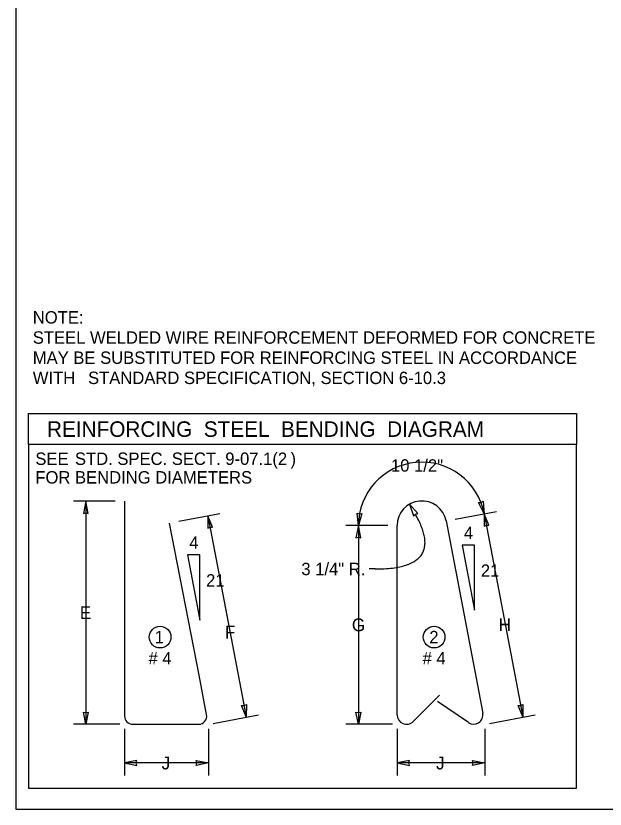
# Model space of a CAD drawing. Extents: x 99862 to 103680, y 99470 to 102076.
# Drawn here: x 99862 to 100621, y 100000 to 101023 of the extents above; entities that cross this region are included whole.
import ezdxf

# ---------------------------------------------------------------- set-up
doc = ezdxf.new("R2010")
doc.units = 0
for name, color, linetype in [('Level 1', 7, 'Continuous'), ('Level 10', 7, 'Continuous'), ('Level 15', 7, 'Continuous'), ('Level 16', 7, 'Continuous'), ('Level 20', 7, 'Continuous'), ('Level 40', 7, 'Continuous'), ('Level 60', 7, 'Continuous')]:
    doc.layers.add(name, color=color, linetype=linetype)

msp = doc.modelspace()

# ---------------------------------------------------------------- linework, layer by layer
at = {"layer": 'Level 1'}
msp.add_lwpolyline([(99862, 99999.5), (103151, 99999.5), (103151, 102075.5), (99862, 102075.5)], close=True, dxfattribs=at)
at = {"layer": 'Level 10'}
for p, q in [((100002.1, 100396.5), (100002.1, 100119.5)), ((100416.4, 100371.2), (100463.6, 100123.2)), ((100353.4, 100121), (100353.4, 100365.2)), ((100407.8, 100146.5), (100373.9, 100112.5)), ((100445.1, 100111.1), (100405.4, 100138.1)), ((100012.6, 100109), (100097.5, 100109))]:
    msp.add_line(p, q, dxfattribs=at)
msp.add_lwpolyline([(100107.8, 100121.5), (100098.1, 100172.2), (100060, 100368.5)], dxfattribs=at)
for centre, radius, start, end in [((100385.2, 100365.2), 31.8, 10.7843, 180), ((100012.6, 100119.5), 10.5, 180, 270), ((100097.5, 100119.5), 10.5, 270, 10.8492), ((100365.4, 100121), 12, 180, 315), ((100451.8, 100121), 12, 235.7843, 10.7843)]:
    msp.add_arc(centre, radius, start, end, dxfattribs=at)
at = {"layer": 'Level 15'}
msp.add_line((100325.1, 100309.2), (100317.1, 100309.2), dxfattribs=at)
msp.add_lwpolyline([(100369.3, 100392.7), (100374.5, 100377.6), (100376.8, 100379.8), (100379.8, 100380.7)], close=True, dxfattribs=at)
for points in [[(100453.1, 100255.9), (100453.1, 100339.9), (100437.1, 100339.9), (100453.1, 100255.9)], [(100099.1, 100243.3), (100099.1, 100327.3), (100083.1, 100327.3), (100099.1, 100243.3)]]:
    msp.add_lwpolyline(points, dxfattribs=at)
msp.add_open_spline([(100325.1, 100309.2), (100417.5, 100309.2), (100376.8, 100379.8)], degree=2, dxfattribs=at)
at = {"layer": 'Level 16'}
for p, q in [((99990.1, 100396.5), (99936.1, 100396.5)), ((99952.1, 100396.5), (99952.1, 100109)), ((100071.8, 100370.7), (100124.9, 100380.8)), ((100428.2, 100373.4), (100481.2, 100383.5)), ((100465.5, 100380.5), (100515.4, 100118.4)), ((100109.5, 100377.9), (100158.9, 100118.4)), ((100341.4, 100365.2), (100287.4, 100365.2)), ((100303.4, 100365.2), (100303.4, 100109)), ((100472.2, 100110.1), (100531.2, 100121.3)), ((99996.1, 100109), (99936.1, 100109)), ((100002.1, 100103), (100002.1, 100043)), ((100347.4, 100109), (100287.4, 100109)), ((100353.4, 100103), (100353.4, 100043)), ((100466.3, 100103), (100466.3, 100043)), ((100466.3, 100059), (100353.4, 100059))]:
    msp.add_line(p, q, dxfattribs=at)
for points in [[(99952.1, 100396.5), (99949, 100380.8), (99952.1, 100381.5), (99955.1, 100380.8)], [(100465.5, 100380.5), (100458.2, 100394.8), (100461.4, 100394.9), (100464.1, 100396.5)], [(100303.4, 100365.2), (100301.8, 100381.2), (100304.8, 100380.2), (100307.9, 100380.6)], [(100465.5, 100380.5), (100465.4, 100364.5), (100468.3, 100365.8), (100471.5, 100365.7)], [(100109.5, 100377.9), (100109.4, 100361.9), (100112.3, 100363.2), (100115.4, 100363)], [(100303.4, 100365.2), (100300.3, 100349.5), (100303.4, 100350.2), (100306.5, 100349.5)], [(100158.9, 100118.4), (100152.9, 100133.2), (100156.1, 100133.1), (100159, 100134.4)], [(100515.4, 100118.4), (100509.5, 100133.2), (100512.6, 100133.1), (100515.5, 100134.4)], [(99952.1, 100109), (99949, 100124.7), (99952.1, 100124), (99955.1, 100124.7)], [(100303.4, 100109), (100300.3, 100124.7), (100303.4, 100124), (100306.5, 100124.7)], [(100353.4, 100059), (100369.1, 100055.9), (100368.4, 100059), (100369.1, 100062.1)], [(100466.3, 100059), (100450.6, 100055.9), (100451.3, 100059), (100450.6, 100062.1)]]:
    msp.add_lwpolyline(points, close=True, dxfattribs=at)
msp.add_arc((100385.2, 100365.2), 81.8, 10.7843, 180, dxfattribs=at)
at = {"layer": 'Level 20'}
for p, q in [((100116.1, 100110.1), (100174.6, 100121.3)), ((100110.2, 100103), (100110.2, 100043)), ((100110.2, 100059), (100002.1, 100059))]:
    msp.add_line(p, q, dxfattribs=at)
for points in [[(100002.1, 100059), (100017.8, 100055.9), (100017, 100059), (100017.8, 100062.1)], [(100110.2, 100059), (100094.4, 100055.9), (100095.2, 100059), (100094.4, 100062.1)]]:
    msp.add_lwpolyline(points, close=True, dxfattribs=at)
for centre in [(100047.8, 100221.4), (100401, 100221.4)]:
    msp.add_circle(centre, 14, dxfattribs=at)
at = {"layer": 'Level 40'}
for points in [[(99878.1, 100509.6), (100584.5, 100509.6), (100584.5, 100469.6), (99878.1, 100469.6)], [(99878.1, 100026.7), (100584.5, 100026.7), (100584.5, 100469.6), (99878.1, 100469.6)]]:
    msp.add_lwpolyline(points, close=True, dxfattribs=at)
at = {"layer": 'Level 60'}
msp.add_line((99862, 99999.5), (99862, 99999.5), dxfattribs=at)

# ---------------------------------------------------------------- texts
at = {"layer": 'Level 15'}
for s, p in [('E', (99944.4, 100244.5)), ('F', (100131.3, 100219.5)), ('G', (100295, 100228.9)), ('H', (100484.2, 100229.1)), ('J', (100049.8, 100050.7)), ('J', (100403.5, 100050.7))]:
    msp.add_text(s, height=16.5, dxfattribs=at).set_placement(p)
at = {"layer": 'Level 20'}
for s, height, p in [('NOTE:', 16, (99883.8, 100625.7)), ('STEEL WELDED WIRE REINFORCEMENT DEFORMED FOR CONCRETE ', 16, (99883.8, 100599.7)), ('MAY BE SUBSTITUTED FOR REINFORCING STEEL IN ACCORDANCE ', 16, (99883.8, 100573.7)), ('WITH ', 16, (99883.8, 100547.7)), ('STANDARD SPECIFICATION, SECTION 6-10.3', 16, (99955, 100547.7)), ('REINFORCING  STEEL  BENDING  DIAGRAM', 19.999, (99902.1, 100479.6)), ('SEE ', 16, (99887.1, 100443.4)), ('STD. SPEC. SECT. 9-07.1(2', 16, (99938.1, 100443.4)), (')', 16, (100215.9, 100443.4)), ('FOR BENDING DIAMETERS', 16, (99887.1, 100419.4)), ('4', 16, (100439.5, 100347.9)), ('4', 16, (100085.5, 100335.3)), ('21', 16, (100461.2, 100299.1)), ('21', 16, (100107.1, 100286.5)), ('1', 16, (100040.9, 100213.4)), ('2', 16, (100394.8, 100213.4)), ('# 4', 16, (100032.9, 100186.1)), ('# 4', 16, (100386.1, 100186.1))]:
    msp.add_text(s, height=height, dxfattribs=at).set_placement(p)
for s, p in [('10 1/2"', (100345.4, 100434.7)), ('3 1/4" R.', (100229.9, 100301.2))]:
    msp.add_text(s, height=16, rotation=360, dxfattribs=at).set_placement(p)

doc.saveas('drawing.dxf')
